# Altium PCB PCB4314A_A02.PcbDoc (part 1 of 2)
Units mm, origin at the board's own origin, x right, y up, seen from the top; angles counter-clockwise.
Board outline 35.56 x 55.88 mm, 2 copper layers (Top Layer, Bottom Layer), stack 1.57 mm thick; 98 components, 71 nets, 413 pads, 418 vias.
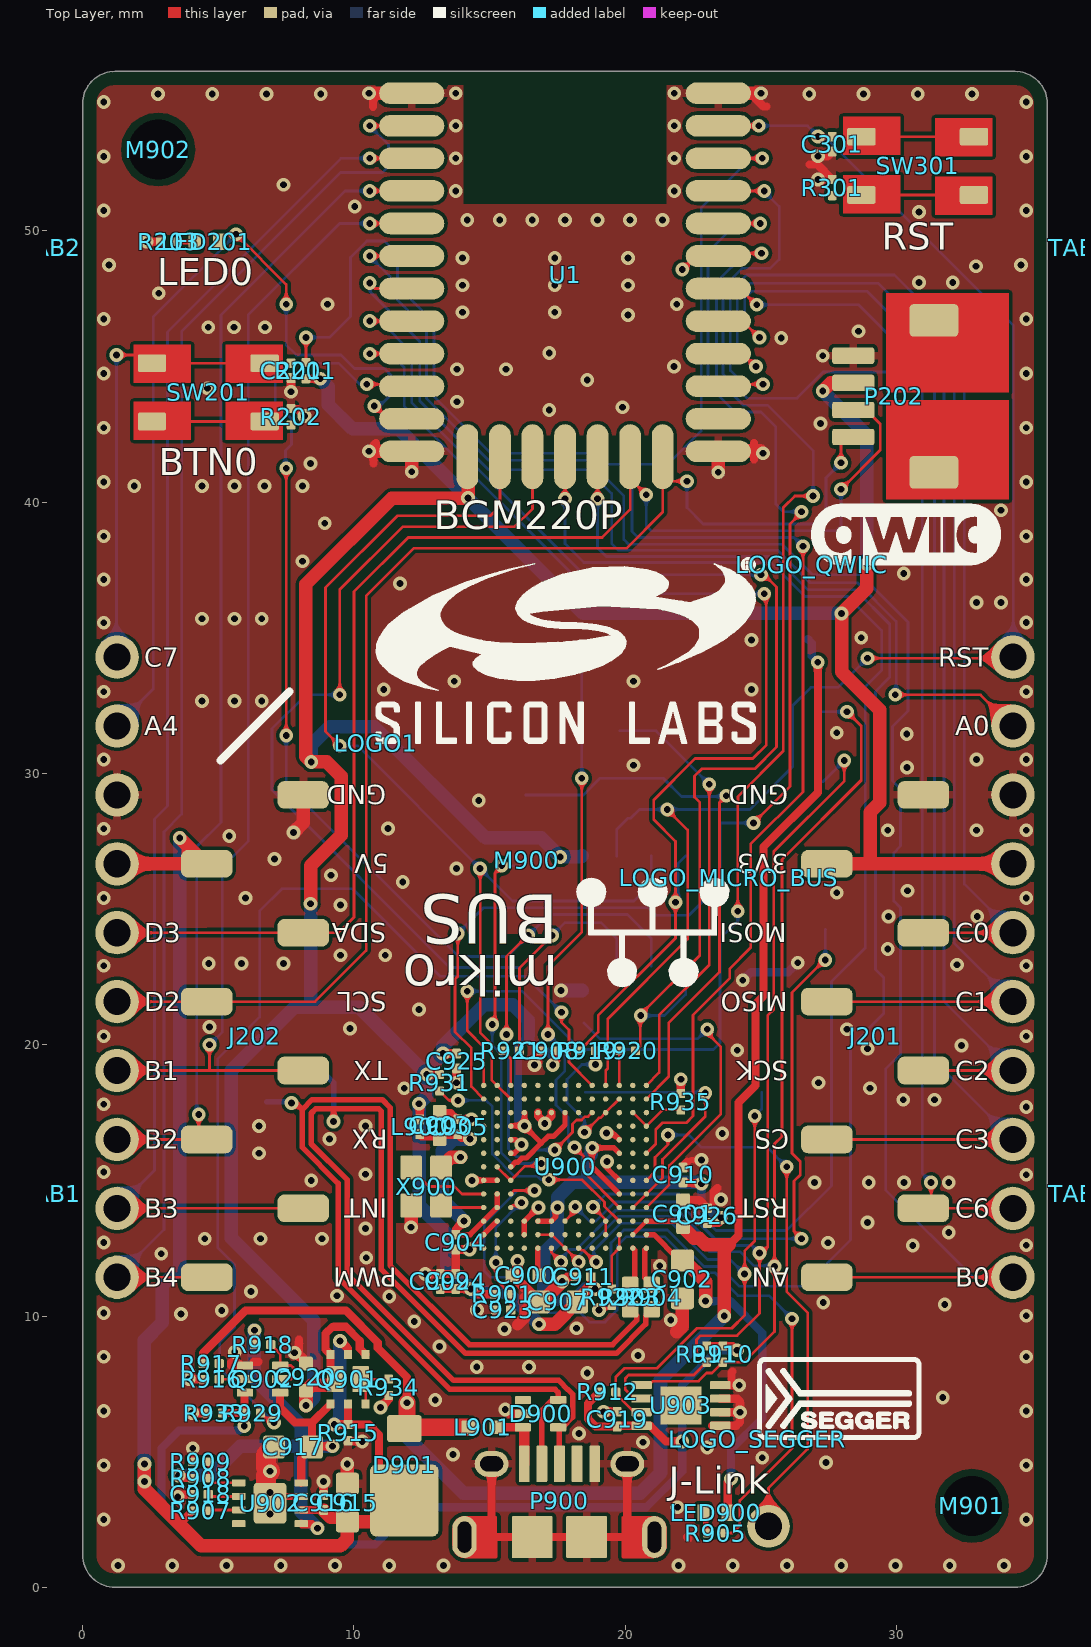
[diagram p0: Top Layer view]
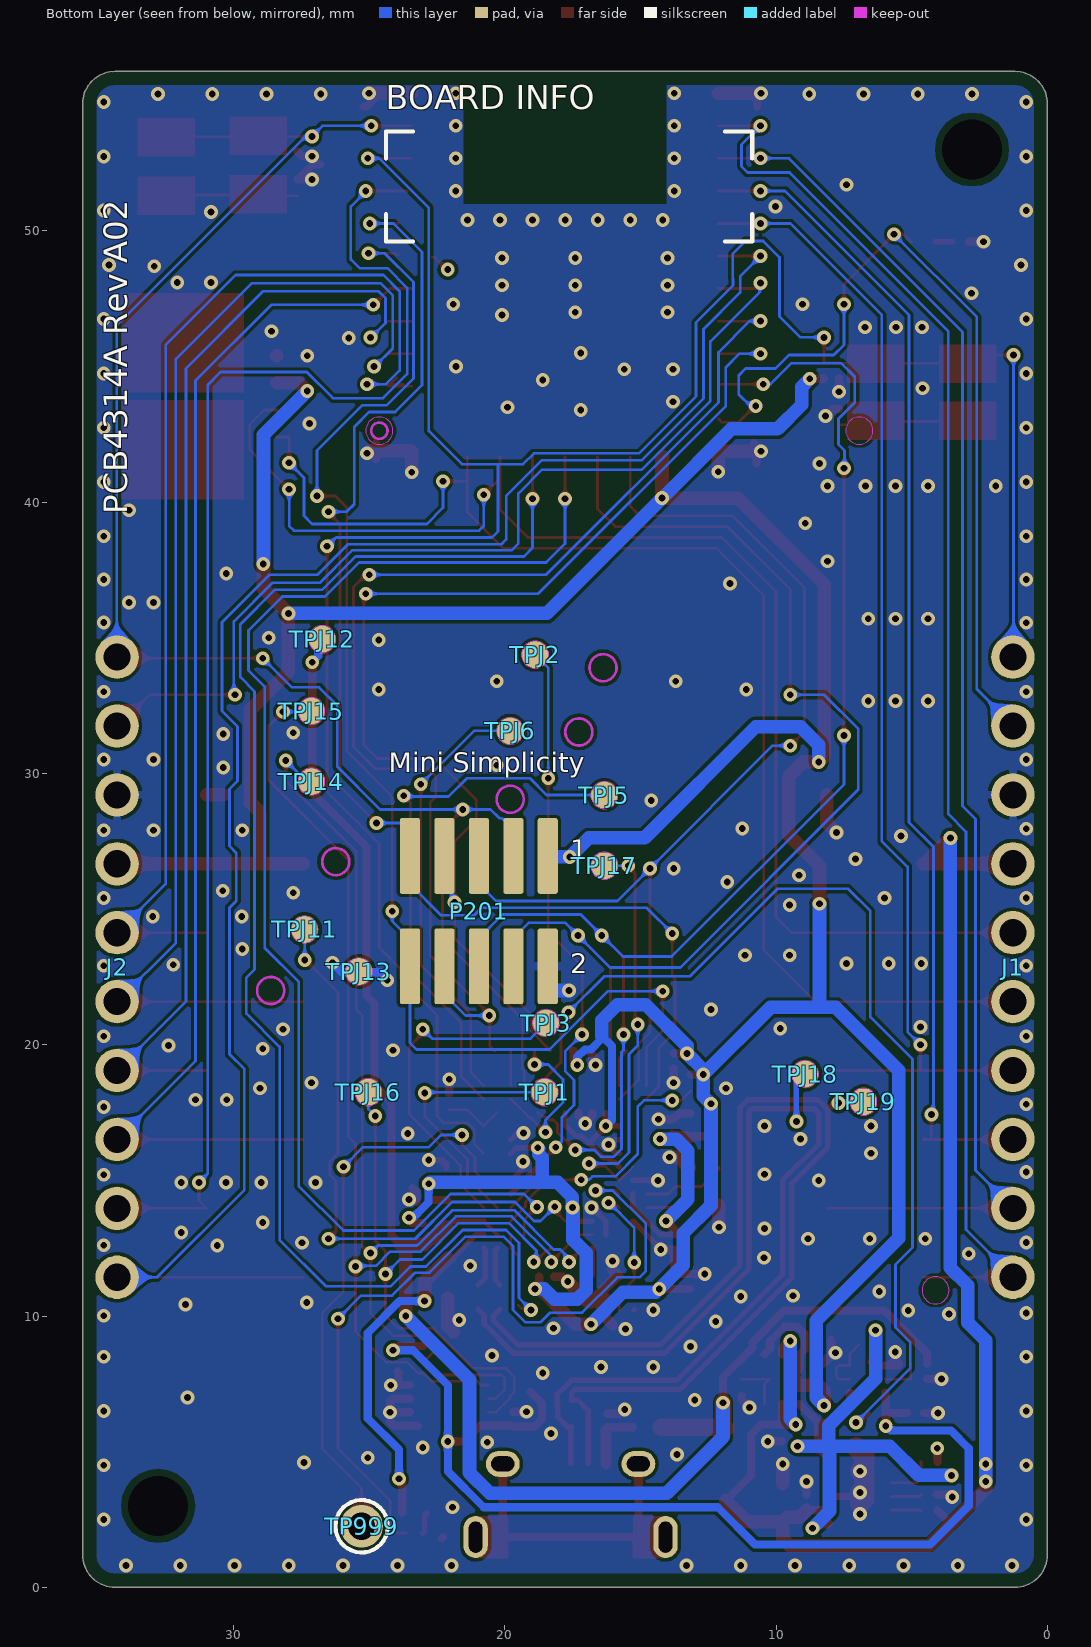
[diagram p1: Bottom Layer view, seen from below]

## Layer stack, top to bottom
Top Solder: solder mask 0.03, Solder Resist, Dk 3.5
Top Layer: signal copper 0.035
Dielectric 1: core 1.5, FR-4, Dk 4.2
Bottom Layer: signal copper 0.035
Bottom Solder: solder mask 0.03, Solder Resist, Dk 3.5

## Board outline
0,1.19 ccw(c1.19,1.191) 1.191,0.001 1.191,0 34.369,0 34.371,0 ccw(c34.371,1.189) 35.56,1.19 35.56,54.693 ccw(c34.371,54.691) 34.369,55.88 1.191,55.88 ccw(c1.189,54.691) 0,54.693

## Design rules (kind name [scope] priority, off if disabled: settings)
AcuteAngle [All] p1: minimum=5.50000000000000E+0001 checktracksonly=FALSE
BoardOutlineClearance [Not HasFootprint('TAB50.5_T1.6_W2.4_SLIM_SL')] p1: gap=0 ignorepadtopadclearanceinfootprint=FALSE except(0.2: THPad-OutlineEdge; 0.4: Via-OutlineEdge Via-CavityEdge Via-CutoutEdge Via-SplitBarrior Via-SplitContinuation; 0.5: THPad-CavityEdge THPad-CutoutEdge THPad-SplitBarrior THPad-SplitContinuation Fill-OutlineEdge Fill-CavityEdge Fill-CutoutEdge Fill-SplitBarrior Fill-SplitContinuation Poly-OutlineEdge Poly-CavityEdge Poly-CutoutEdge Poly-SplitBarrior Poly-SplitContinuation)
Clearance Clearance_Testjigg_TPJ [HasFootprint('TESTJIGG_PCB4166_MECH2_SL') vs InComponent('TPJ*') Or IsTrack] p1: gap=0 ignorepadtopadclearanceinfootprint=FALSE
Clearance USB [InNetClass('USB')] p2: gap=0.127 ignorepadtopadclearanceinfootprint=FALSE except(0: Arc-Hole Track-Hole SMDPad-Hole THPad-Hole Via-Hole Fill-Hole Poly-Hole Region-Hole Text-Hole)
Clearance Clearance_NPL [(ObjectKind = 'Pad') And (Layer = 'MultiLayer') And (Net = 'No Net') And (PadIsPlated = 'False')] p3: gap=0.25 ignorepadtopadclearanceinfootprint=FALSE except(0: Arc-Hole Track-Hole SMDPad-Hole THPad-Hole Via-Hole Fill-Hole Poly-Hole Region-Hole Text-Hole)
Clearance Clearance_General [All] p4: gap=0.125 ignorepadtopadclearanceinfootprint=FALSE except(0: Arc-Hole Track-Hole SMDPad-Hole THPad-Hole Via-Hole Fill-Hole Poly-Hole Region-Hole Text-Hole)
ComponentClearance ComponentClearance_IGNORE [HasFootprint('TESTJIGG_PCB4166_MECH2_SL')] p1: gap=0 collisioncheckmode=3 verticalgap=0 showdistances=FALSE
ComponentClearance [All] p2: gap=0.1 collisioncheckmode=3 verticalgap=0.254 showdistances=FALSE
HoleToHoleClearance HoleToHoleClearance_general [All] p1: gap=0.3 allowstackedmicrovias=TRUE
MinimumSolderMaskSliver [not (InComponent('LOGO_GECKO') OR InComponent('LOGO1'))] p1: minsoldermaskwidth=0.1
PolygonConnect PolygonConnect_general [All] p1: thpad.connectstyle=Relief thpad.reliefconductorwidth=0.3 thpad.reliefentries=4 thpad.polygonreliefangle="90 Angle" thpad.airgapwidth=0.127 smdpad.connectstyle=Relief smdpad.reliefconductorwidth=0.3 smdpad.reliefentries=4 smdpad.polygonreliefangle="90 Angle" smdpad.airgapwidth=0.127 via.connectstyle=Direct via.reliefconductorwidth=0.3 via.reliefentries=4 via.polygonreliefangle="45 Angle" via.airgapwidth=0.2
RoutingVias [All] p1: holewidth=0.25 width=0.508 viastyle="Through Hole" minholewidth=0.25 minwidth=0.508 maxholewidth=1 maxwidth=1.5 useviatemplates=TRUE viatemplateguid#1={61A11D4F-1BCD-4730-B611-ED6A05EB0BD2} viatemplatename#1=v51h25m0mx0
ShortCircuit ShortCircuit_P5toSW4 [Incomponent ('P5') vs Incomponent ('SW4')] p1: allowed=TRUE
ShortCircuit ShortCircuit_ANTtoPAD [InNet('NetAT1_1') vs InNet('GND')] p2: allowed=TRUE
ShortCircuit ShortCircuit_General [All] p3: allowed=FALSE
SilkToSilkClearance [All] p1: silktosilkclearance=0.102
SilkToSolderMaskClearance [IsPad] p1: minsilkscreentomaskgap=0.102 clearancetoexposedcopper=TRUE
SolderMaskExpansion [All] p1: expansion=0.05 istentingtop=FALSE
Width [All] p1: maxlimit=5.08 minlimit=0.1 preferedwidth=0.1
Width Width_USB [InNetClass('USB')] p2: maxlimit=2 minlimit=0.16 preferedwidth=2 toplayer_maxwidth=0.16 toplayer_prefwidth=0.16 bottomlayer_minwidth=2 minimp=50.000000 maximp=50.000000 favimp=50.000000
24 further rules are at their usual default settings.

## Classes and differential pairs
net class USB: CTRL_MCU_PF10 CTRL_MCU_PF11 CTRL_MCU_USB_DM CTRL_MCU_USB_DP
pad class NPL: M901-1 M902-1

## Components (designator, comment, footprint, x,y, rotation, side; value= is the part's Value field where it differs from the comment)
C201 "1N" C0201 7.68,44.85 r270 top
C301 "100N" C0201 27.63,53.2 r270 top
C900 "1U" C0402 16.33,11.5 r180 top
C901 "1U" C0402 22.13,13.775 r90 top
C902 "4U7" C0603 22.106,11.35 r270 top
C903 "1U" C0402 13.155,17.025 r90 top
C904 "10N" C0201 13.755,12.725 r270 top
C905 "10N" C0201 13.83,16.975 r90 top
C907 "4U7" C0603 17.531,10.525 r180 top
C908 "100N" C0201 17.205,19.775 r180 top
C909 "100N" C0201 13.18,11.275 r90 top
C910 "100N" C0201 22.13,15.2 r90 top
C911 "100N" C0201 18.456,11.45 r180 top
C915 "4U7" C0603 9.755,3.125 r90 top
C916 "100N" C0201 8.88,3.125 r90 top
C917 "10U" C0603 7.755,5.175 r180 top
C918 "33N" C0201 4.356,3.425 r180 top
C919 "100N" C0201 19.7,6.2 r90 top
C920 "1U" C0402 8.231,7.75 r90 top
C923 "100N" C0201 15.505,10.225 r180 top
C924 "100N" C0201 13.755,11.275 r90 top
C925 "100N" C0201 13.78,19.4 r270 top
C926 "100N" C0201 23.03,13.7 r90 top
D900 "SP1001-04" SOT553 16.88,6.4 r0 top
D901 "SS3P3" DO220AA 11.855,4.05 r90 top
J1 "1X10_2.54MM" HDR_M254-1X10_NO_3D 1.27,34.29 r270 bottom
J2 "1X10_2.54MM" HDR_M254-1X10_NO_3D 34.29,34.29 r270 bottom
J201 "2185-108" WCON_2185-108M-TYPE2-1X8 29.211,20.32 r90 top locked
J202 "2185-108" WCON_2185-108M-TYPE2-1X8 6.351,20.32 r90 top locked
L900 "742692004" COIL_0201 12.43,16.975 r270 top
L901 "782422221" COIL_0402 14.755,5.9 r180 top
LED201 "Yellow" LED_0402_CAT2 4.58,49.6 r180 top
LED900 "BLUE" LED_0402_CAT2 23.33,2.75 r180 top
LOGO1 "Comment" LOGO_SILABS_W14.0_SILK 10.795,31.115 r0 top locked
LOGO_MICRO_BUS "Comment" LOGO_MICROBUS_GTO_W12.24 23.819,26.15 r180 top locked
LOGO_QWIIC "Comment" LOGO_QWIIC_GTO_W7.0 26.875,37.7 r0 top
LOGO_SEGGER "Comment" LOGO_SEGGER_GTO_W6.0 24.893,5.461 r0 top
M900 "Comment" TESTJIGG_PCB4166_MECH2_SL 18.53,18.25 r0 top locked
M901 "2.2_MM" HOLE_2.2_NPL_SL 32.781,3 r0 top
M902 "2.2_MM" HOLE_2.2_NPL_SL 2.78,53 r0 top
P201 "MINI-SIMPLICITY" FTSH_105_01_L_DV_K 20.956,24.925 r0 bottom locked
P202 "QWIIC_4P" WCON_WF1001A-WM04E-4 31.38,43.9 r270 top
P900 "USB_MICRO-B" FCI_10118194-000_MICRO_USB_B 17.58,0.4 r0 top net-tie
Q901 "SiA527DJ" POWERPAK_SC70-6 9.78,7.675 r90 top
Q902 "DMC2400UV" SOT563 6.63,7.675 r0 top
R201 "1M" R0201 8.23,44.85 r90 top
R202 "100R" R0201 7.68,43.15 r90 top
R203 "2K05" R0201 3.18,49.6 r0 top
R301 "100R" R0201 27.63,51.6 r270 top
R901 "1K" R0201 15.48,10.8 r180 top
R903 "33R" R0402 20.18,10.7 r90 top
R904 "33R" R0402 20.98,10.7 r90 top
R905 "7K5" R0201 23.33,2 r180 top
R907 "10K" R0201 4.356,2.825 r180 top
R908 "180K" R0201 4.356,4.025 r180 top
R909 "110K" R0201 4.356,4.625 r0 top
R910 "4K7" R0201 23.6,8.6 r90 top
R911 "4K7" R0201 23,8.6 r90 top
R912 "10K" R0201 19.35,7.2 r180 top
R915 "470K" R0201 9.781,5.7 r90 top
R916 "100K" R0201 4.731,7.675 r0 top
R917 "1K" R0201 4.731,8.25 r180 top
R918 "330K" R0201 6.63,8.95 r180 top
R919 "470R" R0201 18.605,19.775 r180 top
R920 "470R" R0201 20.081,19.775 r0 top
R921 "470R" R0201 15.805,19.775 r0 top
R922 "470R" R0201 19.506,10.7 r270 top
R929 "1K" R0201 6.255,6.425 r180 top
R931 "1K" R0201 13.155,18.6 r90 top
R933 "4K7" R0201 4.855,6.425 r180 top
R934 "470K" R0201 11.28,7.375 r90 top
R935 "1M" R0201 22.05,17.9 r90 top
SW201 "TS3401" SW_CK_PTS810_SJM_250 4.63,44.05 r0 top
SW301 "TS3401" SW_CK_PTS810_SJM_250 30.78,52.4 r0 top
TAB1 "Comment" TAB50.5_T1.6_W2.4_SLIM__NOHOLES_SL -1.198,14.5 r90 top
TAB2 "Comment" TAB50.5_T1.6_W2.4_SLIM__NOHOLES_SL -1.198,49.38 r90 top
TAB3 "Comment" TAB50.5_T1.6_W2.4_SLIM__NOHOLES_SL 36.76,14.5 r270 top
TAB4 "Comment" TAB50.5_T1.6_W2.4_SLIM__NOHOLES_SL 36.76,49.38 r270 top
TP999 "PROTO_TH" PROTO_TH 25.28,2.25 r180 bottom
TPJ1 "TPJ_SMD" TP_1.0_SMD 18.53,18.25 r90 bottom locked
TPJ2 "TPJ_SMD" TP_1.0_SMD 18.88,34.38 r90 bottom locked
TPJ3 "TPJ_SMD" TP_1.0_SMD 18.48,20.8 r90 bottom locked
TPJ5 "TPJ_SMD" TP_1.0_SMD 16.33,29.2 r90 bottom locked
TPJ6 "TPJ_SMD" TP_1.0_SMD 19.8,31.57 r90 bottom locked
TPJ11 "TPJ_SMD" TP_1.0_SMD 27.38,24.25 r90 bottom locked
TPJ12 "TPJ_SMD" TP_1.0_SMD 26.73,34.95 r90 bottom locked
TPJ13 "TPJ_SMD" TP_1.0_SMD 25.38,22.7 r90 bottom locked
TPJ14 "TPJ_SMD" TP_1.0_SMD 27.13,29.7 r90 bottom locked
TPJ15 "TPJ_SMD" TP_1.0_SMD 27.13,32.3 r90 bottom locked
TPJ16 "TPJ_SMD" TP_1.0_SMD 25.03,18.25 r90 bottom locked
TPJ17 "TPJ_SMD" TP_1.0_SMD 16.33,26.6 r90 bottom locked
TPJ18 "TPJ_SMD" TP_1.0_SMD 8.93,18.92 r90 bottom
TPJ19 "TPJ_SMD" TP_1.0_SMD 6.78,17.9 r90 bottom locked
U1 "BGM220P" MODULE_BGM220P 17.78,48.375 r0 top locked
U900 "EFM32GG12" BGA120_M050_7.0X7.0_EFM32GGR 17.78,15.5 r270 top locked
U902 "LP3982ILD-ADJ" LLP8_MA65_W3.0 6.905,3.1 r180 top
U903 "24AA024" TDFN8_M050_2.0X3.0_EP 22.052,6.705 r180 top locked
X900 "48_MHz" X_SSS_DSX211SH_2.05X1.65-4 12.656,14.775 r90 top

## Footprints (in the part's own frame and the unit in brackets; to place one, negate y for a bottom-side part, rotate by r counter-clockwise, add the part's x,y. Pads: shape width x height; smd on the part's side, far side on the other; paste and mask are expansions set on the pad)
BGA120_M050_7.0X7.0_EFM32GGR [mm] "BGA, 120 Leads, Body 7.0x7.0mmx1,30mm, Pitch 0.50mm (191111)"
  round 0.2 smd mask+0.04: A1(-3,3) A2(-2.5,3) A3(-2,3) A4(-1.5,3) A5(-1,3) A6(-0.5,3) A7(0,3) A8(0.5,3) A9(1,3) A10(1.5,3) A11(2,3) A12(2.5,3) A13(3,3) B1(-3,2.5) B2(-2.5,2.5) B3(-2,2.5) B4(-1.5,2.5) B5(-1,2.5) B6(-0.5,2.5) B7(0,2.5) B8(0.5,2.5) B9(1,2.5) B10(1.5,2.5) B11(2,2.5) B12(2.5,2.5) B13(3,2.5) C1(-3,2) C2(-2.5,2) C3(-2,2) C4(-1.5,2) C5(-1,2) C6(-0.5,2) C7(0,2) C8(0.5,2) C9(1,2) C10(1.5,2) C11(2,2) C12(2.5,2) C13(3,2) D1(-3,1.5) D2(-2.5,1.5) D3(-2,1.5) D11(2,1.5) D12(2.5,1.5) D13(3,1.5) E1(-3,1) E2(-2.5,1) E3(-2,1) E11(2,1) E12(2.5,1) E13(3,1) F1(-3,0.5) F2(-2.5,0.5) F3(-2,0.5) F11(2,0.5) F12(2.5,0.5) F13(3,0.5) G1(-3,0) G2(-2.5,0) G3(-2,0) G11(2,0) G12(2.5,0) G13(3,0) H1(-3,-0.5) H2(-2.5,-0.5) H3(-2,-0.5) H11(2,-0.5) H12(2.5,-0.5) H13(3,-0.5) J1(-3,-1) J2(-2.5,-1) J3(-2,-1) J11(2,-1) J12(2.5,-1) J13(3,-1) K1(-3,-1.5) K2(-2.5,-1.5) K3(-2,-1.5) K11(2,-1.5) K12(2.5,-1.5) K13(3,-1.5) L1(-3,-2) L2(-2.5,-2) L3(-2,-2) L4(-1.5,-2) L5(-1,-2) L6(-0.5,-2) L7(0,-2) L8(0.5,-2) L9(1,-2) L10(1.5,-2) L11(2,-2) L12(2.5,-2) L13(3,-2) M1(-3,-2.5) M2(-2.5,-2.5) M3(-2,-2.5) M4(-1.5,-2.5) M5(-1,-2.5) M6(-0.5,-2.5) M7(0,-2.5) M8(0.5,-2.5) M9(1,-2.5) M10(1.5,-2.5) M11(2,-2.5) M12(2.5,-2.5) M13(3,-2.5) N1(-3,-3) N2(-2.5,-3) N3(-2,-3) N4(-1.5,-3) N5(-1,-3) N6(-0.5,-3) N7(0,-3) N8(0.5,-3) N9(1,-3) N10(1.5,-3) N11(2,-3) N12(2.5,-3) N13(3,-3)
  body extent -3.5,-3.5 3.5,3.5, height 1.3
C0201 [mm] "Capacitor, 9291, HiDens (170502)"
  rrect25% 0.36x0.32 smd paste-0.015: 1(-0.275,0) 2(0.275,0)
  Top Layer pour cut-out: -0.075,-0.2 -0.075,0.2 0.075,0.2 0.075,-0.2
  body extent -0.32,-0.13 0.32,0.13, height 0.3
C0402 [mm] "Chip Capacitor, 2-Leads, Body 1.0x0.5mm, IPC High Density (190308)"
  rrect20% 0.5x0.5 smd mask+0.051: 1(-0.5,0) 2(0.5,0)
  Top Layer pour cut-out: -0.225,-0.3 -0.225,0.3 0.225,0.3 0.225,-0.3
  body extent -0.5,-0.25 0.5,0.25, height 0.6
C0603 [mm] "Capacitor, 0603, HiDens (190130)"
  rrect25% 0.8x0.85 smd: 1(-0.7,0) 2(0.7,0)
  Top Layer pour cut-out: -0.275,-0.55 -0.275,0.55 0.275,0.55 0.275,-0.55
  body extent -0.88,-0.48 0.87,0.48, height 0.95
COIL_0201 [mm] "Inductor, 0201, High Density (C)"
  rrect10% 0.37x0.32 smd: 1(-0.27,0) 2(0.27,0)
  body extent -0.32,-0.17 0.32,0.17, height 0.33
COIL_0402 [mm] "COIL_0402_L (3D from Wurth) (190308)"
  rrect20% 0.55x0.5 smd mask+0.051: 1(-0.525,0) 2(0.525,0)
  body extent -0.5,-0.25 0.5,0.25, height 0.5
DO220AA [mm] "Diode DO220AA (DO-220AA) (= SMP) (Vishay) (170512)"
  rrect20% 2.67x2.54 smd: 1(-0.85,0)
  rrect20% 1x1.27 smd: 2(1.8,0)
  body extent -2,-1.09 2.1,1.09, height 1.15
FCI_10118194-000_MICRO_USB_B [mm] "Amphenol FCI, 10118194-000XLF, Micro USB Type B (171108)"
  rrect20% 0.4x1.35 smd mask+0.076: 1(-1.305,4.15) 2(-0.655,4.15) 3(-0.005,4.15) 4(0.645,4.15) 5(1.295,4.15)
  oval 1.25x0.95 hole 0.55 slot 0.85 at 0 deg: 6(-2.505,4.15) 7(2.495,4.15)
  oval 0.9x1.55 hole 0.5 slot 1.15 at 90 deg paste+0: 8(-3.505,1.45) 9(3.495,1.45)
  rrect5% 1.5x1.55 smd: 10(-1.005,1.45) 11(0.995,1.45)
  Top Layer region: -3.501,0.676 -2.33,0.676 -2.306,0.7 -2.308,2.206 -2.33,2.228 -3.497,2.228 -3.724,2.167 -3.889,2.001 -3.95,1.775 -3.95,1.775 -3.95,1.125 -3.916,0.953 -3.818,0.807 -3.673,0.71 -3.501,0.676
  Top Layer region: 3.476,0.676 2.32,0.676 2.296,0.7 2.298,2.206 2.32,2.228 3.472,2.228 3.711,2.164 3.886,1.989 3.95,1.75 3.95,1.75 3.95,1.15 3.886,0.913 3.713,0.74 3.476,0.676
  body extent -4.05,-1.18 4,4.4, height 3.12
FTSH_105_01_L_DV_K [mm]
  rrect20% 0.74x2.79 smd mask+0.051: 1(-2.54,-2.035) 2(-2.54,2.035) 3(-1.27,-2.035) 4(-1.27,2.035) 5(0,-2.035) 6(0,2.035) 7(1.27,-2.035) 8(1.27,2.035) 9(2.54,-2.035) 10(2.54,2.035)
  body extent -3.23,-3.05 3.22,3.05, height 5.56
HDR_M254-1X10_NO_3D [mm] "No 3D model for this component (180615)"
  round 1.6 hole 1: 1(0,0) 2(2.54,0) 3(5.08,0) 4(7.62,0) 5(10.16,0) 6(12.7,0) 7(15.24,0) 8(17.78,0) 9(20.32,0) 10(22.86,0)
HOLE_2.2_NPL_SL [mm] "HOLE_2.2_NPL (171218)"
  round 0 hole 2.2 unplated: 1(0,0)
LED_0402_CAT2 [mm] "(200921)"
  rrect10% 0.45x0.6 smd: 1(-0.45,0) 2(0.45,0)
  body extent -0.55,-0.33 0.55,0.33, height 0.25
LLP8_MA65_W3.0 [mm] "LLP8_MA65_W3.0 (180615)"
  rrect20% 0.5x0.25 smd: 1(-1.15,0.75) 2(-1.15,0.25) 3(-1.15,-0.25) 4(-1.15,-0.75) 5(1.15,-0.75) 6(1.15,-0.25) 7(1.15,0.25) 8(1.15,0.75)
  rrect20% 1.2x1.5 smd: 9(0,0)
  body extent -1.55,-1.3 1.55,1.3, height 0.8
LOGO_MICROBUS_GTO_W12.24 [mm] "Logo microBUS GTO width 12.24 (200625)"
  silkscreen extent 0,0 5.6,4.01
LOGO_QWIIC_GTO_W7.0 [mm] "Logo QWIIC GTO width 7.0 (200625)"
  silkscreen extent 0,0 6.95,2.22
LOGO_SEGGER_GTO_W6.0 [mm] "Logo SEGGER GTO width 6.0 (200625)"
  silkscreen extent 0,0 6,3
LOGO_SILABS_W14.0_SILK [mm] "LOGO_SILABS_W14.0 SILKSCREEN ONLY"
  silkscreen extent 0.03,0 13.99,6.83
MODULE_BGM220P [mm] "copied from Tamas (200623)"
  oval 2.4x0.8 smd mask+0.051: 1(-5.65,6.7) 2(-5.65,5.5) 3(-5.65,4.3) 4(-5.65,3.1) 5(-5.65,1.9) 6(-5.65,0.7) 7(-5.65,-0.5) 8(-5.65,-1.7) 9(-5.65,-2.9) 10(-5.65,-4.1) 11(-5.65,-5.3) 12(-5.65,-6.5) 21(5.65,-5.3) 22(5.65,-4.1) 23(5.65,-2.9) 24(5.65,-1.7) 25(5.65,-0.5) 26(5.65,0.7) 27(5.65,1.9) 28(5.65,3.1) 29(5.65,4.3) 30(5.65,5.5) 31(5.65,6.7)
  oval 0.8x2.4 smd mask+0.051: 13(-3.6,-6.7) 14(-2.4,-6.7) 15(-1.2,-6.7) 16(0,-6.7) 17(1.2,-6.7) 18(2.4,-6.7) 19(3.6,-6.7)
  oval 2.4x0.8 smd paste+0 mask+0.051: 20(5.65,-6.5)
  Multi-Layer pour cut-out: -3.75,7.5 -3.75,2.6 3.75,2.6 3.75,7.5
  body extent -6.45,-7.5 6.45,7.5, height 2.5
POWERPAK_SC70-6 [mm] "POWERPAK SC70-6 HiDens (Vishay) (170926)"
  rrect10% 0.325x0.3 smd paste-0.025 mask+0.07: 1(-0.913,0.65) 2(-0.913,0) 3(-0.913,-0.65) 4(0.913,-0.65) 5(0.913,0) 6(0.913,0.65)
  rrect10% 0.95x0.613 smd paste-0.025 mask+0.07: 7(0,0.466) 8(0,-0.466)
  body extent -1.02,-1.02 1.02,1.05, height 0.8
PROTO_TH [mil] "Test Point, 1.0 mm (= TP_1.0_D62)"
  round 62 hole 39.37: 1(0,0)
R0201 [mm] "Resistor (Chip2PinSM127P600-8N) (170921)"
  rrect25% 0.34x0.32 smd: 1(-0.3,0) 2(0.3,0)
  Top Layer pour cut-out: -0.1,-0.2 -0.1,0.2 0.1,0.2 0.1,-0.2
  body extent -0.32,-0.13 0.32,0.13, height 0.3
R0402 [mm] "Chip Resistor, 2-Leads, Body 1.0x0.5mm, HiDens (190308)"
  rrect20% 0.6x0.6 smd mask+0.051: 1(-0.45,0) 2(0.45,0)
  Top Layer pour cut-out: -0.125,-0.3 -0.125,0.3 0.125,0.3 0.125,-0.3
  body extent -0.5,-0.25 0.5,0.25, height 0.6
SOT553 [mm] "SOT553 (_M050_W1.2_), 5-Leads, Body 1.60x1.20mm, Pitch 0.5mm, HiDens (180615)"
  rrect25% 0.6x0.3 smd: 1(-0.65,0.5) 2(-0.65,0) 3(-0.65,-0.5) 4(0.65,-0.5) 5(0.65,0.5)
  body extent -0.65,-0.85 0.65,0.85, height 0.6
SOT563 [mm] "SOT563 (_M050_W1.2_), 6-Leads, Body 1.60x1.20, Pitch 0.5, HiDens (170926)"
  rrect25% 0.6x0.3 smd: 1(-0.65,0.5) 2(-0.65,0) 3(-0.65,-0.5) 4(0.65,-0.5) 5(0.65,0) 6(0.65,0.5)
  body extent -0.65,-0.85 0.65,0.85, height 0.6
SW_CK_PTS810_SJM_250 [mm] "Switch C&K PTS810_SJM_250 (grey button) (180319)"
  rrect20% 1.05x0.65 smd: 1(-2.075,1.075) 2(2.075,1.075) 3(-2.075,-1.075) 4(2.075,-1.075)
  body extent -2.29,-1.6 2.29,1.6, height 2.5
TAB50.5_T1.6_W2.4_SLIM__NOHOLES_SL [mm] "TAB50.5_T1.6_W2.4 no holes (200921)"
TDFN8_M050_2.0X3.0_EP [mm] "TDFN8_M050_2.0x3.0_EP (170921)"
  rrect20% 0.75x0.3 smd: 1(-1.45,0.75) 2(-1.45,0.25) 3(-1.45,-0.25) 4(-1.45,-0.75) 5(1.45,-0.75) 6(1.45,-0.25) 7(1.45,0.25) 8(1.45,0.75)
  rect 1.5x1.4 smd: 9(0,0)
  body extent -1.5,-1 1.5,1, height 1.01
TESTJIGG_PCB4166_MECH2_SL [mm]
  round 1 on Mech2: 7(-14.41,-7.3) 7(-11.75,-0.35) 7(-11.596,24.385) 7(-9.6,0.67) 7(-2.2,8.35) 7(-2.2,10.95) 7(-2.15,15.65) 7(-1.26,13.28) 7(-0.05,2.55) 7(0,0) 7(0.35,16.13) 7(1.27,10.8) 7(1.27,13.32) 7(6.095,24.385) 7(6.5,0) 7(6.85,4.45) 7(7.7,8.5) 7(8.2,16.7) 7(8.6,11.45) 7(8.6,14.05) 7(8.85,6) 7(10.1,3.75)
  rect 6.7x6.7 on Mech2: 9(-6.8,7.3)
  Bottom Layer keep-out region: 6.095,24.885 6.345,24.818 6.528,24.635 6.595,24.385 6.595,24.385 6.528,24.135 6.345,23.952 6.095,23.885 6.095,23.885 5.845,23.952 5.662,24.135 5.595,24.385 5.595,24.385 5.662,24.635 5.845,24.818 6.095,24.885
  Bottom Layer keep-out region: -11.596,24.885 -11.346,24.818 -11.163,24.635 -11.096,24.385 -11.096,24.385 -11.163,24.135 -11.346,23.952 -11.596,23.885 -11.596,23.885 -11.846,23.952 -12.029,24.135 -12.096,24.385 -12.096,24.385 -12.029,24.635 -11.846,24.818 -11.596,24.885
  Bottom Layer keep-out region: 0.35,16.63 0.6,16.563 0.783,16.38 0.85,16.13 0.85,16.13 0.783,15.88 0.6,15.697 0.35,15.63 0.35,15.63 0.1,15.697 -0.083,15.88 -0.15,16.13 -0.15,16.13 -0.083,16.38 0.1,16.563 0.35,16.63
  Bottom Layer keep-out region: -2.15,16.15 -1.9,16.083 -1.717,15.9 -1.65,15.65 -1.65,15.65 -1.717,15.4 -1.9,15.217 -2.15,15.15 -2.15,15.15 -2.4,15.217 -2.583,15.4 -2.65,15.65 -2.65,15.65 -2.583,15.9 -2.4,16.083 -2.15,16.15
  Bottom Layer keep-out region: 1.27,13.82 1.52,13.753 1.703,13.57 1.77,13.32 1.77,13.32 1.703,13.07 1.52,12.887 1.27,12.82 1.27,12.82 1.02,12.887 0.837,13.07 0.77,13.32 0.77,13.32 0.837,13.57 1.02,13.753 1.27,13.82
  Bottom Layer keep-out region: -1.26,13.78 -1.01,13.713 -0.827,13.53 -0.76,13.28 -0.76,13.28 -0.827,13.03 -1.01,12.847 -1.26,12.78 -1.26,12.78 -1.51,12.847 -1.693,13.03 -1.76,13.28 -1.76,13.28 -1.693,13.53 -1.51,13.713 -1.26,13.78
  Bottom Layer keep-out region: 1.27,11.3 1.52,11.233 1.703,11.05 1.77,10.8 1.77,10.8 1.703,10.55 1.52,10.367 1.27,10.3 1.27,10.3 1.02,10.367 0.837,10.55 0.77,10.8 0.77,10.8 0.837,11.05 1.02,11.233 1.27,11.3
  Bottom Layer keep-out region: -2.2,11.45 -1.95,11.383 -1.767,11.2 -1.7,10.95 -1.7,10.95 -1.767,10.7 -1.95,10.517 -2.2,10.45 -2.2,10.45 -2.45,10.517 -2.633,10.7 -2.7,10.95 -2.7,10.95 -2.633,11.2 -2.45,11.383 -2.2,11.45
  Bottom Layer keep-out region: -2.2,8.85 -1.95,8.783 -1.767,8.6 -1.7,8.35 -1.7,8.35 -1.767,8.1 -1.95,7.917 -2.2,7.85 -2.2,7.85 -2.45,7.917 -2.633,8.1 -2.7,8.35 -2.7,8.35 -2.633,8.6 -2.45,8.783 -2.2,8.85
  Bottom Layer keep-out region: 8.2,17.2 8.45,17.133 8.633,16.95 8.7,16.7 8.7,16.7 8.633,16.45 8.45,16.267 8.2,16.2 8.2,16.2 7.95,16.267 7.767,16.45 7.7,16.7 7.7,16.7 7.767,16.95 7.95,17.133 8.2,17.2
  Bottom Layer keep-out region: 8.6,14.55 8.85,14.483 9.033,14.3 9.1,14.05 9.1,14.05 9.033,13.8 8.85,13.617 8.6,13.55 8.6,13.55 8.35,13.617 8.167,13.8 8.1,14.05 8.1,14.05 8.167,14.3 8.35,14.483 8.6,14.55
  Bottom Layer keep-out region: 8.6,11.95 8.85,11.883 9.033,11.7 9.1,11.45 9.1,11.45 9.033,11.2 8.85,11.017 8.6,10.95 8.6,10.95 8.35,11.017 8.167,11.2 8.1,11.45 8.1,11.45 8.167,11.7 8.35,11.883 8.6,11.95
  Bottom Layer keep-out region: 7.7,9 7.95,8.933 8.133,8.75 8.2,8.5 8.2,8.5 8.133,8.25 7.95,8.067 7.7,8 7.7,8 7.45,8.067 7.267,8.25 7.2,8.5 7.2,8.5 7.267,8.75 7.45,8.933 7.7,9
  Bottom Layer keep-out region: 8.85,6.5 9.1,6.433 9.283,6.25 9.35,6 9.35,6 9.283,5.75 9.1,5.567 8.85,5.5 8.85,5.5 8.6,5.567 8.417,5.75 8.35,6 8.35,6 8.417,6.25 8.6,6.433 8.85,6.5
  Bottom Layer keep-out region: 10.1,4.25 10.35,4.183 10.533,4 10.6,3.75 10.6,3.75 10.533,3.5 10.35,3.317 10.1,3.25 10.1,3.25 9.85,3.317 9.667,3.5 9.6,3.75 9.6,3.75 9.667,4 9.85,4.183 10.1,4.25
  Bottom Layer keep-out region: 6.85,4.95 7.1,4.883 7.283,4.7 7.35,4.45 7.35,4.45 7.283,4.2 7.1,4.017 6.85,3.95 6.85,3.95 6.6,4.017 6.417,4.2 6.35,4.45 6.35,4.45 6.417,4.7 6.6,4.883 6.85,4.95
  Bottom Layer keep-out region: 6.5,0.5 6.75,0.433 6.933,0.25 7,0 7,0 6.933,-0.25 6.75,-0.433 6.5,-0.5 6.5,-0.5 6.25,-0.433 6.067,-0.25 6,0 6,0 6.067,0.25 6.25,0.433 6.5,0.5
  Bottom Layer keep-out region: -0.05,3.05 0.2,2.983 0.383,2.8 0.45,2.55 0.45,2.55 0.383,2.3 0.2,2.117 -0.05,2.05 -0.05,2.05 -0.3,2.117 -0.483,2.3 -0.55,2.55 -0.55,2.55 -0.483,2.8 -0.3,2.983 -0.05,3.05
  Bottom Layer keep-out region: 0,0.5 0.25,0.433 0.433,0.25 0.5,0 0.5,0 0.433,-0.25 0.25,-0.433 0,-0.5 0,-0.5 -0.25,-0.433 -0.433,-0.25 -0.5,0 -0.5,0 -0.433,0.25 -0.25,0.433 0,0.5
  Bottom Layer keep-out region: -9.6,1.17 -9.35,1.103 -9.167,0.92 -9.1,0.67 -9.1,0.67 -9.167,0.42 -9.35,0.237 -9.6,0.17 -9.6,0.17 -9.85,0.237 -10.033,0.42 -10.1,0.67 -10.1,0.67 -10.033,0.92 -9.85,1.103 -9.6,1.17
  Bottom Layer keep-out region: -11.75,0.15 -11.5,0.083 -11.317,-0.1 -11.25,-0.35 -11.25,-0.35 -11.317,-0.6 -11.5,-0.783 -11.75,-0.85 -11.75,-0.85 -12,-0.783 -12.183,-0.6 -12.25,-0.35 -12.25,-0.35 -12.183,-0.1 -12,0.083 -11.75,0.15
  Bottom Layer keep-out region: -14.41,-6.8 -14.16,-6.867 -13.977,-7.05 -13.91,-7.3 -13.91,-7.3 -13.977,-7.55 -14.16,-7.733 -14.41,-7.8 -14.41,-7.8 -14.66,-7.733 -14.843,-7.55 -14.91,-7.3 -14.91,-7.3 -14.843,-7.05 -14.66,-6.867 -14.41,-6.8
TP_1.0_SMD [mm] "Test Point, 1.0 mm, SMD (170509)"
  round 1 smd paste-0.501: 1(0,0)
WCON_2185-108M-TYPE2-1X8 [mm] "WCON 2185-108M TYPE2 (200623)"
  rrect50% 1.02x1.905 smd: 1(-8.89,1.778) 2(-6.35,-1.778) 3(-3.81,1.778) 4(-1.27,-1.778) 5(1.27,1.778) 6(3.81,-1.778) 7(6.35,1.778) 8(8.89,-1.778)
  body extent -10.16,-1.27 10.16,1.27, height 8.5
WCON_WF1001A-WM04E-4 [mm] "WCON, WF1001A-WM04ER1 4-terminal H: 4.87 (200622)"
  rrect25% 0.6x1.55 smd: 1(-1.5,-2.975) 2(-0.5,-2.975) 3(0.5,-2.975) 4(1.5,-2.975)
  rrect25% 1.2x1.8 smd: 5(-2.8,0) 6(2.8,0)
  body extent -3.15,-2.2 3.15,0.7, height 4.91
X_SSS_DSX211SH_2.05X1.65-4 [mm] "X_SSS_DSX211SH_2.05X1.65-4"
  rrect20% 0.9x0.8 smd: 1(-0.7,-0.55) 2(0.7,-0.55) 3(0.7,0.55) 4(-0.7,0.55)
  body extent -1.07,-0.87 1.07,0.87, height 0.51

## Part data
LED900: library part Blue

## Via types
v1: diameter 0.508, hole 0.25, Top Layer to Bottom Layer, tented both sides, 418 vias

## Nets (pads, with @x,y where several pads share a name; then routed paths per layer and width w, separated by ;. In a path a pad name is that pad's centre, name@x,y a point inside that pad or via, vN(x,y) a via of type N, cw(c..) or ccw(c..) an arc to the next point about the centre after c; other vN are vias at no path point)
3V3: C917.1 Q901.1 Q902.4 R908.2 R918.2 U902.1 U902.4 | length 22.2
  Top Layer w0.3: v1(3.531,4.125) 3.587,4.125 3.677,4.035 4.046,4.035 R908.2@4.056,4.025 ; R918.2@6.33,8.95 6.331,8.951 v1(6.331,9.475) ; Q902.4@7.28,7.175 7.28,6.626 7.831,6.075 8.455,6.075 ; U902.1@8.055,2.35 8.08,2.325 8.45,2.325 8.6,2.175 v1(8.656,2.175) ; U902.4@8.055,3.85 8.055,4.75 8.455,5.15 C917.1@8.455,5.175 8.455,6.075 ; C917.1@8.48,5.2 v1(9.206,5.2) ; Q901.1@9.13,6.763 9.13,6.75 8.455,6.075
  Top Layer w0.5: C917.1@8.455,5.175 C917.1@8.48,5.2
  Bottom Layer w0.5: v1(3.531,4.125) 4.731,4.125 5.806,5.2 8.031,5.2 8.031,2.8 v1(8.656,2.175) ; v1(6.331,9.475) 6.331,7.69 8.056,5.965 8.056,5.2 v1(9.206,5.2)
5V: C915.1 C916.1 D901.1 J1.4 J202.7 Q901.2 Q901.5 R907.2 R915.2 U902.2 | length 53.8
  Top Layer w0.3: 3.563,2.337 3.569,2.337 R907.2@4.056,2.825 ; U902.2@8.055,2.85 C916.1@8.88,2.85 ; v1(9.275,6) R915.2@9.781,6 ; v1@9.481,9.1 9.78,8.801 Q901.5@9.78,8.588 ; Q901.2@9.78,6.763 9.78,6.001 R915.2@9.781,6 ; D901.1@11.855,3.2 10.925,4.13 10.925,5.625 10.55,6 R915.2@9.781,6
  Top Layer w0.5: J1.4@1.246,26.67 J202.7@3.9,26.67 ; v1(2.275,4.541) v1(2.275,3.9) 2.275,3.625 3.563,2.337 4.375,1.525 9.5,1.525 9.755,1.78 C915.1@9.755,2.425 ; v1(3.575,27.625) 3.9,27.3 ; J202.7@4.573,26.67 J202.7@4.53,26.67 ; C916.1@8.88,2.845 9.15,2.575 9.605,2.575 C915.1@9.755,2.425 ; D901.1@11.855,3.2 11.08,2.425 C915.1@9.755,2.425 ; J202.7@3.9,26.67 3.9,27.3 ; J202.7@3.9,26.67 J202.7@4.53,26.67 ; 3.9,27.3 J202.7@4.53,26.67
  Bottom Layer w0.5: v1(2.275,3.9) v1(2.275,4.541) 2.275,9.1 2.937,9.763 2.937,11.137 3.575,11.775 v1(3.575,27.625) ; v1(9.275,6) 9.481,6.206 v1(9.481,9.075)
BGM220P_BUTTON0: C201.1 J1.1 R201.2 SW201.1 SW201.2 U1.29 U900.A6 | length 90
  Top Layer w0.1: v1(1.25,45.425) 2.255,45.425 SW201.1@2.555,45.125 SW201.2@6.705,45.125 C201.1@7.68,45.125 7.692,45.137 8.217,45.137 R201.2@8.23,45.15 v1(8.231,46.075) ; U900.A6@20.78,16 21.125,16.345 21.125,16.875 21.375,17.125 22.25,17.125 22.5,17.375 22.5,21.1 23.85,22.45 23.85,22.8 24.625,23.575 24.625,27.4 26.55,29.325 26.55,30.6 v1(26.55,38.375) ; U1.29@23.43,52.675 v1(25.05,52.675) v1@25.15,52.675
  Bottom Layer w0.1: J1.1@1.246,34.29 1.246,45.421 v1(1.25,45.425) ; v1(8.231,46.075) 9.1,46.075 9.875,46.85 9.875,49.025 10.475,49.625 11.125,49.625 11.601,49.149 11.601,48.247 11.589,48.236 11.589,47.986 12.95,46.625 12.95,43.9 15.05,41.8 18.929,41.8 19.329,41.4 20.25,41.4 ; v1(25.05,52.675) 24.625,52.675 22.8,50.85 22.8,42.625 21.575,41.4 20.25,41.4 ; v1@26.612,38.437 26.488,38.437 26.225,38.7 20.475,38.7 20.25,38.925 20.25,41.4
BGM220P_LED0: J1.2 LED201.1 U1.11 | length 33
  Top Layer w0.1: LED201.1@5.03,49.6 5.305,49.875 v1(5.65,49.875) 5.681,49.844 7.5,48.025 v1(7.5,47.3) ; v1(10.75,43.55) 10.775,43.55 11.375,42.95 12.005,42.95 U1.11@12.13,43.075
  Bottom Layer w0.1: J1.2@1.246,31.75 2.6,33.104 2.6,46.825 v1(5.65,49.875) ; v1(7.5,47.3) 7.5,45.8 7.875,45.425 9.525,45.425 10.025,44.925 11.125,44.925 11.375,44.675 11.375,43.975 10.95,43.55 v1(10.75,43.55)
BGM220P_PA00: J2.2 U1.7 | length 36.2
  Top Layer w0.1: v1@10.579,48.05 10.754,47.875 U1.7@12.13,47.875 ; v1(29.95,32.9) 33.1,32.9 J2.2@34.3,31.7
  Bottom Layer w0.1: v1@10.6,47.975 10.6,47.75 12.425,45.925 12.425,43.725 14.95,41.2 18.625,41.2 19.5,40.325 19.5,38.475 19.75,38.225 25.625,38.225 26.82,37.03 28.555,37.03 29.988,35.598 29.988,32.938 v1(29.95,32.9)
  other v1: 10.579,48.075
BGM220P_PA01: P201.8 R920.2 U1.8 | length 44.8
  Top Layer w0.1: v1(10.579,46.675) U1.8@12.13,46.675 ; R920.2@20.381,19.775 20.55,19.944 20.55,21.1 22.75,23.3 22.75,28.925 22.55,29.125 22.55,29.9 22.825,30.175 24.775,30.175 25.575,30.975 25.575,36.875 25.125,37.325 v1(25,37.325)
  Bottom Layer w0.1: v1(10.579,46.675) 10.975,46.675 12.125,45.525 12.125,43.675 18.475,37.325 v1(25,37.325)
  Bottom Layer w0.102: v1(20.575,21.075) 21.45,21.075 22.226,21.851 P201.8@22.226,22.425
BGM220P_PA02: P201.7 R919.2 U1.9 | length 44.1
  Top Layer w0.1: v1(10.579,45.475) U1.9@12.13,45.475 ; R919.2@18.305,19.775 19,20.47 19,21.075 21.85,23.925 v1(21.85,25.25) 21.85,27.5 21.05,28.3 21.05,29.025 22.575,30.55 24.7,30.55 25.2,31.05 v1@25.2,36.6
  Bottom Layer w0.1: v1(10.579,45.475) 11.35,45.475 11.85,44.975 11.85,43.55 18.775,36.625 v1(25.125,36.625) ; v1(21.85,25.25) 21.95,25.35 21.95,26.684 P201.7@22.226,26.96 P201.7@22.231,26.955
BGM220P_PA03: P201.6 U1.10 U900.E3 | length 51.3
  Top Layer w0.1: v1(7.5,31.4) v1(7.5,41.25) v1@7.5,41.275 ; v1@10.5,44.35 U1.10@12.13,44.35 ; v1@17.402,16.123 18.055,16.775 18.055,17.075 18.205,17.225 18.394,17.225 18.519,17.35 18.63,17.35 U900.E3@18.78,17.5
  Top Layer w0.102: v1(15.625,20.375) 15.625,23.25 16.4,24.025 v1(16.425,24.025)
  Bottom Layer w0.1: v1@7.475,41.325 7.475,41.9 7.7,42.125 7.7,43.075 7.1,43.675 7.1,44.625 7.6,45.125 9.425,45.125 10.2,44.35 v1(10.475,44.35) ; v1@7.5,31.42 7.5,30.475 7.5,29.6 13.85,23.25 15.65,23.25 v1(16.425,24.025) 17.2,24.8 20.081,24.8 20.956,23.925 P201.6@20.956,22.89
  Bottom Layer w0.102: v1(15.625,20.375) 15.625,19.8 15.7,19.725 15.7,16.156 15.981,15.875 16.45,15.875 16.7,16.125 v1(17.4,16.125)
BGM220P_PA05: P201.5 U1.14 U900.L2 U900.M1 | length 39.6
  Top Layer w0.1: v1(9.475,31.025) 8.95,31.55 8.95,36.85 11.6,39.5 15.025,39.5 15.38,39.855 U1.14@15.38,41.675 ; v1(14.65,26.5) 14.65,20.45 15.075,20.025 15.075,18.705 U900.M1@15.28,18.5 U900.L2@15.78,18
  Bottom Layer w0.1: v1(9.475,31.025) 10.125,31.025 v1(14.65,26.5) 15.85,25.3 20.325,25.3 20.956,25.931 P201.5@20.956,26.96
BGM220P_PA06: P201.4 R921.2 U1.15 | length 41.5
  Top Layer w0.1: v1(9.475,32.9) 9.475,36.775 11.8,39.1 15.925,39.1 16.58,39.755 U1.15@16.58,41.675 ; R921.2@16.105,19.775 16.105,22.83 v1(17.3,24.025)
  Bottom Layer w0.1: v1(9.475,32.9) 8.225,32.9 6.975,31.65 6.975,29.4 13.525,22.85 16.125,22.85 v1(17.3,24.025) 17.775,24.5 19.1,24.5 19.686,23.914 P201.4@19.686,22.89
BGM220P_PA07: U1.16 U900.D11 U900.D12 | length 48.9
  Top Layer w0.1: v1(17.78,40.124) U1.16@17.78,41.675 ; v1@18.804,14.038 19.28,13.562 U900.D11@19.28,13.5 U900.D12@19.28,13
  Bottom Layer w0.1: v1(17.78,40.124) 17.78,38.47 18.475,37.775 25.375,37.775 26.625,36.525 28.2,36.525 29.45,35.275 29.45,33.8 28.85,33.2 28.85,23.575 27.6,22.325 27.6,14.8 25.95,13.15 23.35,13.15 22,14.5 19.29,14.5 v1(18.808,14.018)
BGM220P_PA08: R922.2 U1.17 | length 52.6
  Top Layer w0.1: v1(18.98,40.124) U1.17@18.98,41.675 ; v1(19.031,10.225) 19.086,10.279 19.386,10.279 R922.2@19.506,10.4
  Bottom Layer w0.1: v1(18.98,40.124) 18.98,38.32 19.3,38 25.5,38 26.725,36.775 28.475,36.775 29.75,35.5 29.75,33.55 29.225,33.025 29.225,22.775 29.528,22.472 29.528,21.153 28.3,19.925 28.3,12.8 26.6,11.1 24.2,11.1 23.475,11.825 22.9,11.825 21.55,13.175 19.95,13.175 19.475,12.7 19.475,10.669 v1(19.031,10.225)
BGM220P_PB00: J2.10 J201.1 U1.6 | length 64.4
  Top Layer w0.1: v1(10.579,49.075) U1.6@12.13,49.075 ; J201.1@27.433,11.43 J2.10@34.29,11.43
  Bottom Layer w0.1: v1(10.579,49.075) 10.577,49.073 11.325,48.325 11.325,47.725 12.675,46.375 12.675,43.825 14.95,41.55 18.625,41.55 19.95,40.225 19.95,38.625 20.125,38.45 25.775,38.45 26.9,37.325 28.675,37.325 30.425,35.575 30.425,32.3 29.85,31.725 29.85,29.725 30.15,29.425 30.15,27.325 29.9,27.075 29.9,25.3 30.15,25.05 30.15,19.65 29.6,19.1 29.6,14.65 32.82,11.43 J2.10@34.29,11.43
BGM220P_PB01: J1.7 J202.4 U1.5 | length 42.8
  Top Layer w0.1: J1.7@1.246,19.05 J1.7@1.27,19.05 4.573,19.05 4.675,19.05 ; v1(4.675,20) 4.675,19.05 ; J202.4@8.129,19.05 4.675,19.05 ; v1(10.579,50.275) U1.5@12.13,50.275
  Bottom Layer w0.1: v1(4.675,20) 5.15,20.475 5.15,26.55 6.1,27.5 6.1,46.9 9.475,50.275 v1(10.579,50.275)
BGM220P_PB02: J1.8 J202.3 U1.4 | length 43.1
  Top Layer w0.1: J1.8@1.246,16.51 J1.8@1.27,16.51 J202.3@4.3,16.51 ; v1(4.275,17.425) 4.275,16.535 J202.3@4.3,16.51 ; J202.3@4.525,16.558 J202.3@4.573,16.51 J202.3@4.3,16.51 ; v1(10.579,51.475) U1.4@12.13,51.475
  Bottom Layer w0.1: v1(4.275,17.425) 4.2,17.5 4.2,27.3 5.1,28.2 5.1,46.9 9.675,51.475 v1(10.579,51.475)
BGM220P_PB03: J1.9 J202.2 U1.3 | length 51.6
  Top Layer w0.1: J1.9@1.246,13.97 J1.9@1.27,13.97 4.573,13.97 J202.2@8.129,13.97 ; v1(10.579,52.675) U1.3@12.13,52.675
  Bottom Layer w0.1: J1.9@1.246,13.97 2.65,15.374 2.65,28.325 3.125,28.8 3.125,46.275 9.525,52.675 v1(10.579,52.675)
BGM220P_PB04: J1.10 J202.1 U1.2 | length 52.7
  Top Layer w0.1: J1.10@1.246,11.43 J1.10@1.27,11.43 J202.1@4.573,11.43 ; v1(10.579,53.875) U1.2@12.13,53.875
  Bottom Layer w0.1: J1.10@1.246,11.43 3,13.184 3,27.85 3.65,28.5 3.65,46.3 9.5,52.15 11.05,52.15 11.275,52.375 11.275,53.179 v1(10.579,53.875)
BGM220P_PC00: J2.5 J201.6 U1.22 | length 42.7
  Top Layer w0.1: U1.22@23.43,44.275 U1.22@23.675,44.275 ; U1.22@23.988,44.588 U1.22@24.225,44.35 ; v1(25.075,44.35) U1.22@24.225,44.35 ; J201.6@30.989,24.13 J2.5@34.29,24.13 ; U1.22@23.675,44.275 24.3,44.275 U1.22@24.225,44.35 ; U1.22@23.675,44.275 23.75,44.35 U1.22@24.225,44.35
  Bottom Layer w0.1: v1(25.075,44.35) 24.375,44.35 23.875,44.85 23.875,47.775 24.475,48.375 29.925,48.375 32.5,45.8 32.5,25.921 J2.5@34.29,24.13
BGM220P_PC01: J2.6 J201.5 U1.23 | length 45.3
  Top Layer w0.1: U1.23@23.43,45.475 24.325,45.475 24.8,45 v1(24.825,45) ; J201.5@27.433,21.59 J2.6@34.29,21.59
  Bottom Layer w0.1: v1(24.825,45) 24.8,45 24.125,45.675 24.125,47.625 24.575,48.075 29.325,48.075 32.125,45.275 32.125,23.756 J2.6@34.29,21.59
BGM220P_PC02: J2.7 J201.4 U1.24 | length 42.3
  Top Layer w0.1: U1.24@23.43,46.675 24.325,46.675 v1@24.9,46.1 ; J201.4@30.989,19.05 J2.7@34.29,19.05
  Bottom Layer w0.1: v1(24.95,46.075) 24.925,46.075 24.4,46.6 24.4,47.525 24.65,47.775 28.906,47.775 31.75,44.931 31.75,21.591 J2.7@34.29,19.05
BGM220P_PC03: J2.8 J201.3 U1.25 | length 45.4
  Top Layer w0.1: U1.25@23.43,47.875 24.225,47.875 v1@24.825,47.275 ; J201.3@27.433,16.51 J2.8@34.29,16.51
  Bottom Layer w0.1: v1(24.85,47.275) 28.6,47.275 28.603,47.278 31.4,44.481 31.4,19.401 J2.8@34.29,16.51
BGM220P_PC04: P201.10 U1.26 U900.N1 | length 49.9
  Top Layer w0.1: v1(14.175,21.975) 14.175,20.525 14.78,19.92 U900.N1@14.78,18.5 ; v1(22.1,48.575) 22.125,48.575 22.575,49.025 U1.26@22.675,49.025 ; U1.26@23.95,49.1 24.025,49.175 v1(25.025,49.175) ; v1(24.15,24.925) 24.15,28.993 24.154,28.997 24.154,29.154 25.825,30.825 25.825,39.8 26.25,40.225 v1(26.925,40.225)
  Bottom Layer w0.1: v1(14.175,21.975) 16.2,21.975 18.35,19.825 23.25,19.825 23.496,20.071 P201.10@23.496,22.89 23.496,23.915 24.15,24.569 v1(24.15,24.925) ; v1(25.025,49.175) 24.425,49.175 23.363,48.113 23.363,44.562 24.35,43.575 25.25,43.575 26.925,41.9 v1(26.925,40.225)
BGM220P_PC05: P201.9 U1.27 U900.N2 | length 49.2
  Top Layer w0.1: v1(13.825,24.1) 13.825,22.525 13.725,22.425 13.725,20.475 14.325,19.875 14.325,18.455 U900.N2@14.78,18 ; U1.27@23.925,50.3 23.95,50.275 v1(24.975,50.275) ; v1(24.725,28.175) 26.075,29.525 26.075,30.625 26.075,39.2 v1@26.5,39.625
  Bottom Layer w0.1: v1(13.825,24.1) 14.775,25.05 20.85,25.05 21.125,24.775 22.35,24.775 23.496,25.921 P201.9@23.496,26.96 ; 23.045,44.32 24.045,43.32 ; 23.05,44.325 23.05,49.225 24.1,50.275 v1(24.975,50.275) ; P201.9@23.496,27.871 P201.9@23.496,26.96 ; 24.05,43.325 25,43.325 25.55,42.775 25.55,39.925 25.825,39.65 v1(26.5,39.65) ; v1(24.725,28.175) 23.496,28.175 P201.9@23.496,26.96
BGM220P_PC06: J2.9 J201.2 U1.28 | length 52.2
  Top Layer w0.1: U1.28@23.6,51.45 23.625,51.475 v1(25.125,51.475) ; v1(31.275,14.925) 31.275,14.256 J201.2@30.989,13.97 J2.9@34.29,13.97
  Bottom Layer w0.1: v1@25.125,51.45 25.675,50.9 25.675,48.95 25.35,48.625 24.325,48.625 23.6,47.9 23.6,44.725 24.492,43.833 26.333,43.833 27.3,44.8 30.475,44.8 30.95,44.325 30.95,15.25 v1(31.275,14.925)
BGM220P_PD02: J1.6 J202.5 P202.4 U1.19 | length 48.3
  Top Layer w0.1: J1.6@1.246,21.59 J1.6@1.27,21.59 8.129,21.59 8.565,21.59 10.45,23.475 10.45,36.55 12.2,38.3 20.05,38.3 21.38,39.63 U1.19@21.38,40.82 ; U1.19@21.38,41.075 U1.19@21.38,40.82 ; U1.19@21.38,41.675 21.38,41.12 U1.19@21.425,41.075 ; v1(22.275,40.775) 21.425,40.775 U1.19@21.38,40.82 ; v1(27.95,41.45) 27.95,42.4 P202.4@28.405,42.4
  Bottom Layer w0.1: v1(22.275,40.775) 22.275,39.8 22.875,39.2 27.1,39.2 27.4,39.5 27.4,40.9 v1(27.95,41.45)
BGM220P_PD03: J1.5 J202.6 P202.3 U1.18 | length 49.2
  Top Layer w0.1: J1.5@1.246,24.13 J1.5@1.27,24.13 4.573,24.13 9.43,24.13 10,24.7 10,36.7 12,38.7 19.15,38.7 20.18,39.73 U1.18@20.18,40.87 ; U1.18@20.18,41.675 U1.18@20.18,40.87 ; v1(20.775,40.275) U1.18@20.18,40.87 ; v1(27.95,40.475) 29.4,41.925 29.4,42.875 28.875,43.4 P202.3@28.405,43.4
  Bottom Layer w0.1: v1(20.775,40.275) 20.775,39.125 20.95,38.95 27.775,38.95 27.95,39.125 v1(27.95,40.475)
BGM220P_RESETN: C301.1 J2.1 P201.3 SW301.1 SW301.2 U1.30 U900.D1 | length 63.2
  Top Layer w0.1: U900.D1@19.28,18.5 19.28,19.042 19.356,19.118 19.356,20.956 22.3,23.9 22.3,27.921 v1(21.546,28.675) ; U1.30@23.43,53.875 v1(24.925,53.875) ; v1(27.106,53.475) C301.1@27.63,53.475 SW301.1@28.705,53.475 SW301.2@32.855,53.475 ; v1(28.925,34.25) 34.251,34.25 J2.1@34.29,34.29
  Bottom Layer w0.1: P201.3@19.686,26.96 19.686,27.936 20.1,28.35 20.2,28.35 20.525,28.675 v1(21.546,28.675) 24.6,28.675 26.175,30.25 26.175,32.5 26.85,33.175 27.85,33.175 v1(28.925,34.25) ; v1(24.925,53.875) 26.725,53.875 v1@27.1,53.5 ; v1(27.106,53.475) 27.35,53.475 34.3,46.525 34.3,34.299 J2.1@34.29,34.29
BOARD_ID_SCL: R911.1 TPJ14.1 U900.H13 U903.6 | length 40.5
  Top Layer w0.1: U900.H13@17.28,12.5 17.28,12.343 v1(17.631,11.992) ; U903.6@20.602,6.955 20.345,6.955 20,7.3 20,7.7 20.125,7.825 22.525,7.825 R911.1@23,8.3 22.625,8.675 22.625,9.125 22.775,9.275 24.125,9.275 24.95,10.1 24.95,12.288 v1(24.95,12.325) ; v1@24.988,12.288 25.25,12.55 25.25,21.075 25.475,21.3 25.475,27.125 28.075,29.725 v1(28.075,30.475)
  Bottom Layer w0.1: v1@17.565,12.059 17.956,12.45 18.2,12.45 19.65,13.9 21.931,13.9 23.206,12.624 23.226,12.624 23.25,12.6 24.675,12.6 v1(24.95,12.325) ; TPJ14.1@27.13,29.7 27.3,29.7 v1(28.075,30.475)
BOARD_ID_SDA: R910.1 TPJ15.1 U900.G13 U900.H12 U900.J12 U903.5 | length 41.8
  Top Layer w0.1: U900.J12@16.78,13 U900.H12@17.28,13 U900.G13@17.78,12.5 v1@18.205,12.075 ; U903.5@20.602,7.455 20.873,7.455 21.018,7.6 22.7,7.6 23,7.9 23.2,7.9 R910.1@23.6,8.3 24.375,8.3 25.5,9.425 v1(25.5,11.825) 25.5,16.35 25.775,16.625 25.775,26.825 28.7,29.75 28.7,31.75 v1(28.175,32.275)
  Bottom Layer w0.1: v1@18.188,11.992 18.188,12.113 19.75,13.675 21.8,13.675 23.1,12.375 24.225,12.375 24.75,11.85 25.5,11.85 v1@25.525,11.825 ; TPJ15.1@27.13,32.3 27.155,32.275 v1(28.175,32.275)
  other v1: 18.288,11.992
BOARD_ID_WP: R912.1 TPJ16.1 U900.F13 U903.7 | length 24.1
  Top Layer w0.1: U900.F13@18.28,12.5 18.307,12.5 18.386,12.421 18.47,12.421 18.897,11.994 v1@18.932,11.994 ; U903.7@20.602,6.455 20.32,6.455 19.8,6.975 19.8,7.05 R912.1@19.65,7.2 19.65,7.75 19.975,8.075 21.175,8.075 22.65,9.55 23.925,9.55 24.4,10.025 v1(24.4,11.55) 24.4,12.4 24.775,12.775 v1(24.775,17.375)
  Bottom Layer w0.1: v1@18.832,11.994 18.832,12.407 19.85,13.425 21.7,13.425 23.038,12.088 23.862,12.088 v1(24.4,11.55) ; v1(24.775,17.375) 25.03,17.63 TPJ16.1@25.03,18.25
  other v1: 18.932,11.992
CTRL_MCU_PA0: R919.1 U900.C2 U900.D3 | length 5.8
  Top Layer w0.1: v1(18.5,16.775) 19.032,17.307 19.087,17.307 U900.D3@19.28,17.5 U900.C2@19.78,18
  Top Layer w0.102: R919.1@18.905,19.775 18.905,19.276 v1(18.906,19.275)
  Bottom Layer w0.102: v1(18.5,16.775) 18.5,17.225 17.85,17.875 17.85,18.725 18.4,19.275 v1(18.906,19.275)
CTRL_MCU_PA1: R920.1 U900.C1 | length 1.3
  Top Layer w0.102: U900.C1@19.78,18.5 R920.1@19.781,19.774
